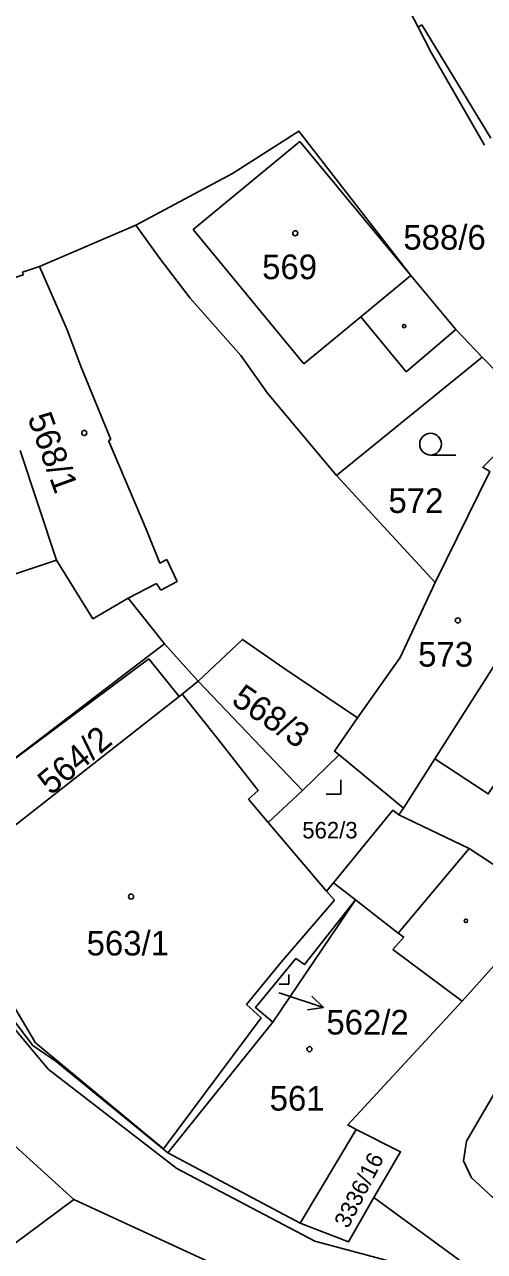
# Model space of a CAD drawing. Extents: x -600849 to -599899, y -1204328 to -1203436.
# Drawn here: x -600680.6 to -600648.8, y -1203729.5 to -1203644.8 of the extents above; entities that cross this region are included whole.
import ezdxf

# ---------------------------------------------------------------- set-up
doc = ezdxf.new("R2010")
doc.units = 0
for name, color, linetype in [('Vrstva 1', 7, 'Continuous'), ('Vrstva 2', 7, 'Continuous'), ('Vrstva 3', 7, 'Continuous'), ('Vrstva 4', 7, 'Continuous'), ('Vrstva 5', 7, 'Continuous'), ('Vrstva 7', 7, 'Continuous')]:
    doc.layers.add(name, color=color, linetype=linetype)

msp = doc.modelspace()

# ---------------------------------------------------------------- linework, layer by layer
at = {"layer": 'Vrstva 1'}
for p, q in [((-600659.01, -1203675.94), (-600648.97, -1203667.78)), ((-600645.18, -1203671.67), (-600648.97, -1203667.78)), ((-600678.34, -1203681.79), (-600680.85, -1203674.22)), ((-600652.21, -1203683.34), (-600659.01, -1203675.94)), ((-600670.89, -1203687.56), (-600668.56, -1203690.14)), ((-600661.36, -1203697.7), (-600668.56, -1203690.14)), ((-600658.83, -1203695.24), (-600661.36, -1203697.7)), ((-600658.83, -1203695.24), (-600654.39, -1203698.92)), ((-600654.39, -1203698.92), (-600654.71, -1203699.37)), ((-600659.22, -1203704.07), (-600657.71, -1203705.24)), ((-600657.71, -1203705.24), (-600663.41, -1203713.69)), ((-600663.41, -1203713.69), (-600670.66, -1203722.71)), ((-600678.37, -1203716.41), (-600670.66, -1203722.71)), ((-600677.14, -1203725.93), (-600683.88, -1203719.83)), ((-600661.52, -1203727.56), (-600657.66, -1203721.1)), ((-600670.66, -1203722.71), (-600661.52, -1203727.56)), ((-600642.08, -1203736.28), (-600656.44, -1203725.8)), ((-600681.3, -1203729), (-600677.14, -1203725.93)), ((-600677.14, -1203725.93), (-600663.39, -1203732.27))]:
    msp.add_line(p, q, dxfattribs=at)
for points in [[(-600843.16, -1203547.591), (-600840.17, -1203550.97), (-600827.54, -1203564.68), (-600820.22, -1203571.95), (-600772.49, -1203617.73), (-600738.37, -1203650.36), (-600721.29, -1203666.47), (-600702.75, -1203684.47), (-600689.43, -1203700.21), (-600686.84, -1203705.75), (-600685.14, -1203709.49), (-600678.92, -1203716.93), (-600670.04, -1203723.78), (-600660.52, -1203728.8)], [(-600657.14, -1203637.78), (-600656.17, -1203639.63), (-600653.39, -1203645), (-600652.48, -1203646.75), (-600648.8, -1203653.13)], [(-600648.97, -1203667.78), (-600650.78, -1203665.87), (-600653.88, -1203662.14), (-600661.61, -1203652.16), (-600666.2, -1203655.09), (-600672.88, -1203658.65)], [(-600672.88, -1203658.65), (-600679.51, -1203661.52), (-600680.7, -1203661.91), (-600680.64, -1203662.09), (-600683.56, -1203663.09), (-600683.65, -1203662.85), (-600684.49, -1203663.12)], [(-600659.01, -1203675.94), (-600663.78, -1203670.26), (-600665.62, -1203667.67), (-600669.13, -1203663.71), (-600671.22, -1203660.96), (-600672.88, -1203658.65)], [(-600652.21, -1203683.34), (-600648.44, -1203675.66), (-600648.93, -1203675.37), (-600645.18, -1203671.67)], [(-600654.39, -1203698.92), (-600652.23, -1203695.5), (-600648.55, -1203697.93), (-600647.84, -1203696.87), (-600647.4, -1203697.17), (-600641.76, -1203687.77), (-600642.34, -1203687.32), (-600641.83, -1203686.53), (-600642.93, -1203685.78), (-600641.88, -1203681.53), (-600638.57, -1203682.87), (-600636.9, -1203680.79)], [(-600693.4, -1203686.7), (-600685.99, -1203684.33), (-600678.34, -1203681.79)], [(-600678.34, -1203681.79), (-600675.83, -1203685.83), (-600673.39, -1203684.42), (-600670.89, -1203687.56)], [(-600657.56, -1203692.68), (-600654.63, -1203688.5), (-600652.21, -1203683.34)], [(-600688.84, -1203699.22), (-600683.27, -1203697), (-600683.24, -1203696.99), (-600671.27, -1203687.84), (-600670.89, -1203687.56)], [(-600668.56, -1203690.14), (-600665.52, -1203687.26), (-600662.66, -1203689.25), (-600657.56, -1203692.68)], [(-600668.56, -1203690.14), (-600669.68, -1203691.05), (-600669.88, -1203691.21), (-600685.76, -1203703.66)], [(-600657.56, -1203692.68), (-600659.16, -1203694.97), (-600658.83, -1203695.24)], [(-600659.22, -1203704.07), (-600659.7, -1203704.63), (-600663.74, -1203699.9), (-600661.36, -1203697.7)], [(-600654.71, -1203699.37), (-600655.13, -1203699.06), (-600659.22, -1203704.07)], [(-600644.23, -1203705.39), (-600649.87, -1203701.7), (-600654.71, -1203699.37)], [(-600686.85, -1203704.49), (-600684.75, -1203709.06), (-600679.99, -1203715.3), (-600678.37, -1203716.41)], [(-600657.71, -1203705.24), (-600661.24, -1203709.71), (-600661.83, -1203709.29), (-600664.61, -1203712.68), (-600663.41, -1203713.69)], [(-600657.66, -1203721.1), (-600658.25, -1203720.78), (-600650.34, -1203712.23), (-600644.23, -1203705.39)], [(-600644.4, -1203712.2), (-600650.04, -1203721.89), (-600650.26, -1203723.26), (-600649.7, -1203724.43), (-600648.27, -1203725.74), (-600646.68, -1203726.45), (-600645.35, -1203726.69), (-600644.1, -1203726.69), (-600642.45, -1203726.38), (-600632.91, -1203721.42), (-600634.37, -1203719.62)], [(-600657.66, -1203721.1), (-600654.61, -1203722.63), (-600656.44, -1203725.8)], [(-600656.44, -1203725.8), (-600658.19, -1203728.84), (-600661.52, -1203727.56)], [(-600660.52, -1203728.8), (-600653.29, -1203730.73), (-600647.36, -1203734), (-600642.88, -1203737.29), (-600614.1, -1203765.81), (-600602.89, -1203776.26)]]:
    msp.add_lwpolyline(points, dxfattribs=at)
at = {"layer": 'Vrstva 3'}
for p, q in [((-600652.523, -1203674.53), (-600650.773, -1203674.53)), ((-600658.73, -1203697.95), (-600658.73, -1203696.95)), ((-600659.731, -1203697.95), (-600658.73, -1203697.95)), ((-600662.31, -1203711.07), (-600662.31, -1203710.4)), ((-600662.981, -1203711.07), (-600662.31, -1203711.07))]:
    msp.add_line(p, q, dxfattribs=at)
msp.add_circle((-600652.523, -1203673.78), 0.75, dxfattribs=at)
at = {"layer": 'Vrstva 4'}
for p, q in [((-600653.39, -1203645), (-600653.13, -1203644.84)), ((-600653.13, -1203644.84), (-600648.36, -1203652.65)), ((-600661.55, -1203652.88), (-600668.91, -1203658.96)), ((-600661.55, -1203652.88), (-600653.88, -1203662.14)), ((-600668.91, -1203658.96), (-600661.27, -1203668.23)), ((-600679.51, -1203661.52), (-600677.62, -1203665.89)), ((-600657.35, -1203665), (-600653.88, -1203662.14)), ((-600661.27, -1203668.23), (-600657.35, -1203665)), ((-600657.35, -1203665), (-600654.22, -1203668.78)), ((-600677.62, -1203665.89), (-600676.65, -1203668.47)), ((-600654.22, -1203668.78), (-600650.78, -1203665.87)), ((-600676.65, -1203668.47), (-600674.59, -1203673.46)), ((-600674.75, -1203673.53), (-600674.59, -1203673.46)), ((-600672.15, -1203679.64), (-600674.75, -1203673.53)), ((-600671.21, -1203682), (-600672.15, -1203679.64)), ((-600671.21, -1203682), (-600670.74, -1203681.74)), ((-600670.74, -1203681.74), (-600670.01, -1203683.27)), ((-600673.39, -1203684.42), (-600671.44, -1203683.39)), ((-600671.15, -1203683.85), (-600671.44, -1203683.39)), ((-600670.01, -1203683.27), (-600671.15, -1203683.85)), ((-600652.23, -1203695.5), (-600645.38, -1203684.72)), ((-600683.24, -1203696.99), (-600671.97, -1203688.6)), ((-600671.97, -1203688.6), (-600669.88, -1203691.21)), ((-600669.68, -1203691.05), (-600667.24, -1203694.11)), ((-600667.24, -1203694.11), (-600664.42, -1203697.69)), ((-600664.42, -1203697.69), (-600665.1, -1203698.3)), ((-600665.1, -1203698.3), (-600663.74, -1203699.9)), ((-600654.76, -1203707.54), (-600649.87, -1203701.7)), ((-600659.7, -1203704.63), (-600659.15, -1203705.27)), ((-600659.15, -1203705.27), (-600662.84, -1203709.55)), ((-600657.71, -1203705.24), (-600654.76, -1203707.54)), ((-600654.38, -1203707.81), (-600655.14, -1203708.67)), ((-600654.76, -1203707.54), (-600654.38, -1203707.81)), ((-600655.14, -1203708.67), (-600650.34, -1203712.23)), ((-600662.84, -1203709.55), (-600665.24, -1203712.46)), ((-600679.79, -1203715.12), (-600682.03, -1203711.34)), ((-600665.24, -1203712.46), (-600664.22, -1203713.39)), ((-600664.22, -1203713.39), (-600670.97, -1203722.43)), ((-600678.32, -1203716.34), (-600679.79, -1203715.12)), ((-600670.97, -1203722.43), (-600678.32, -1203716.34))]:
    msp.add_line(p, q, dxfattribs=at)
at = {"layer": 'Vrstva 5'}
for centre, radius in [((-600661.867, -1203659.219), 0.175), ((-600654.345, -1203665.629), 0.117), ((-600676.427, -1203673.009), 0.175), ((-600650.647, -1203685.949), 0.175), ((-600673.197, -1203705.019), 0.175), ((-600650.085, -1203706.689), 0.117), ((-600660.887, -1203715.549), 0.175)]:
    msp.add_circle(centre, radius, dxfattribs=at)
at = {"layer": 'Vrstva 7'}
for p, q in [((-600663.01, -1203711.66), (-600662.77, -1203711.74)), ((-600662.77, -1203711.74), (-600659.916, -1203712.667)), ((-600659.916, -1203712.667), (-600660.714, -1203711.882)), ((-600659.916, -1203712.667), (-600661.023, -1203712.834))]:
    msp.add_line(p, q, dxfattribs=at)

# ---------------------------------------------------------------- texts
at = {"layer": 'Vrstva 2'}
for s, height, p in [('588/6', 1.7, (-600654.407, -1203660.35)), ('569', 1.7, (-600664.155, -1203662.39)), ('572', 1.7, (-600655.435, -1203678.53)), ('573', 1.7, (-600653.385, -1203689.14)), ('562/3', 1.14, (-600661.381, -1203701)), ('563/1', 1.7, (-600676.268, -1203709.08)), ('562/2', 1.7, (-600659.72, -1203714.538)), ('561', 1.7, (-600663.635, -1203719.79))]:
    msp.add_text(s, height=height, dxfattribs=at).set_placement(p)
for s, height, rotation, p in [('568/1', 1.7, 290, (-600680.366, -1203671.951)), ('568/3', 1.7, 326, (-600666.359, -1203691.66)), ('564/2', 1.7, 40, (-600678.74, -1203698.071)), ('3336/16', 1.14, 63, (-600658.221, -1203727.985))]:
    msp.add_text(s, height=height, rotation=rotation, dxfattribs=at).set_placement(p)

doc.saveas('drawing.dxf')
